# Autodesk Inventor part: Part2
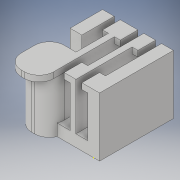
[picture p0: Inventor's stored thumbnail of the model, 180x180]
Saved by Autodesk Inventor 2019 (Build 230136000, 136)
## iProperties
Created: 2019-02
Part Number: Part2
Material: Generic
Document SubType Name: Modeling
Designer: Patel Family
Density: 1 g/cm^3
Appearance: Default
Author: Patel Family
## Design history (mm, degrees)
sketch "Sketch3"
  geometry: 1 further point
sketch "Sketch4"
  geometry: L1 (0, 0)-(10, 0); L2 (10, 0)-(10, -12.5); L3 (10, -12.5)-(0, -12.5); L4 (0, -12.5)-(0, 0)
  constraints: 8 end point, 2 parallel, 1 horizontal, 1 perpendicular
  dimensions: "d12" = 10 distance of L2.end L3.end; "d13" = 12.5 distance of L1.end L2.end
extrude "Extrusion2" new body sketch "Sketch4" distance "d14" = 2; taper "d15" = 0 deg
sketch "Sketch5"
  geometry: 1 further point
sketch "Sketch6"
  geometry: L1 (-10, 0)-(0, 0) reference; L2 (0, 0)-(-1, 0); L3 (-1, 0)-(-3, 0); L4 (-3, 0)-(-4, 0); L5 (-4, 0)-(-6, 0); L6 (-6, 0)-(-7, 0); L7 (-7, 0)-(-9, 0); L8 (-9, 0)-(-10, 0); L9 (0, 12.5)-(-10, 12.5) reference; L10 (0, 0)-(-1, 0); L11 (-1, 0)-(-1, 12.5); L12 (-1, 12.5)-(0, 12.5); L13 (0, 12.5)-(0, 0); L14 (-3, 0)-(-4, 0); L15 (-4, 0)-(-4, 12.5); L16 (-4, 12.5)-(-3, 12.5); L17 (-3, 12.5)-(-3, 0); L18 (-6, 0)-(-7, 0); L19 (-7, 12.5)-(-6, 12.5); L20 (-6, 12.5)-(-6, 0); L21 (-9, 0)-(-10, 0); L22 (-10, 0)-(-10, 12.5); L23 (-10, 12.5)-(-9, 12.5); L24 (-6, 0)-(-10, 0); L25 (-10, 0)-(-10, 4); L26 (-6, 4)-(-6, 0); L27 (-10, 12.5)-(-9, 12.5); L28 (-9, 12.5)-(-9, 6.5); L29 (-9, 6.5)-(-10, 6.5); L30 (-10, 6.5)-(-10, 12.5); L31 (-10, 4)-(-7, 4); L32 (-7, 4)-(-7, 12.5)
  constraints: 60 end point, 10 point on line, 9 parallel, 6 horizontal, 6 perpendicular, 1 collinear
  dimensions: "d16" = 1 distance of L1.end L2.end; "d17" = 2 distance of L2.end L3.end; "d18" = 1 distance of L3.end L4.end; "d19" = 2 distance of L4.end L5.end; "d20" = 1 distance of L5.end L6.end; "d21" = 2 distance of L6.end L7.end; "d22" = 1 distance of L7.end L1.start (derived); "d23" = 4 distance of L24.end L25.end; "d24" = 6 distance of L27.end L28.end
extrude "Extrusion3" join sketch "Sketch6" distance "d25" = 8; taper "d26" = 0 deg
sketch "Sketch7"
  geometry: L1 (0, 10)-(4, 10) reference; L2 (4, 2)-(4, 10) reference; L3 (0, 10)-(4, 10); L4 (4, 10)-(4, 9); L5 (4, 9)-(0, 9); L6 (0, 9)-(0, 10); 1 further point
  constraints: 8 end point, 2 parallel, 1 horizontal, 1 perpendicular, 1 point on line
  dimensions: "d27" = 1 distance of L3.end L4.end
extrude "Extrusion4" join sketch "Sketch7" distance "d28" = 2; taper "d29" = 0 deg
fillet "Fillet2" dims "d31" = 1
sketch "Sketch8"
  geometry: L1 (12.5, 0)-(12.5, 8) reference; L2 (8.5, 9)-(8.5, 1) reference
  dimensions: "d32" = 4 distance between parallel lines of L1 L2 (derived)
sketch "Sketch9"
  geometry: 1 further point
sketch "Sketch10"
  geometry: L1 (0, 10)-(8.5, 10) reference; L2 (12.5, 0)-(12.5, 10) reference; L3 (8.5, 10)-(12.5, 10); L4 (12.5, 10)-(12.5, 0); L5 (12.5, 0)-(8.5, 0); L6 (8.5, 0)-(8.5, 10)
  constraints: 8 end point, 2 parallel, 1 horizontal, 1 perpendicular
sketch "Sketch11"
  geometry: 1 further point
sketch "Sketch13"
  geometry: L1 (8.5, 2)-(8.5, 10) reference; L2 (8.5, 10)-(12.5, 10); L3 (12.5, 10)-(12.5, 0); L4 (12.5, 0)-(8.5, 0); L5 (8.5, 0)-(8.5, 10)
  constraints: 8 end point, 2 parallel, 1 horizontal, 1 perpendicular
extrude "Extrusion6" join sketch "Sketch13" distance "d36" = 1.5; taper "d37" = 0 deg
sketch "Sketch14"
  geometry: L1 (-7, 8)-(-8.5, 8) reference; L2 (-3, 0)-(-1, 0) reference; L3 (-8.5, 8)-(-3, 8); L4 (-3, 8)-(-3, 0); L5 (-3, 0)-(-8.5, 0); L6 (-8.5, 0)-(-8.5, 8); L7 (3, -2)-(-8.5, -2) reference; L8 (-3, -2)-(-8.5, -2); L9 (-8.5, -2)-(-8.5, 0); L10 (-8.5, 0)-(-3, 0); L11 (-3, 0)-(-3, -2)
  constraints: 16 end point, 4 parallel, 2 horizontal, 2 perpendicular, 2 point on line
extrude "Extrusion7" join sketch "Sketch14" distance "d38" = 1.5; taper "d39" = 0 deg
fillet "Fillet3" dims "d40" = 2.5
sketch "Sketch15"
  geometry: L1 (-4, 8)-(-3, 8) reference; L2 (-8.5, -2)-(-8.5, 8) reference; L3 (-3, 8)-(-8.5, 8); L4 (-8.5, 8)-(-8.5, 7); L5 (-8.5, 7)-(-3, 7); L6 (-3, 7)-(-3, 8); 1 further point
  constraints: 8 end point, 2 parallel, 1 horizontal, 1 perpendicular, 1 point on line
  dimensions: "d41" = 1 distance of L4.end L3.end
extrude "Extrusion8" join sketch "Sketch15" stored distance "d42" = 3.5; taper "d43" = 0 deg
fillet "Fillet4" dims "d44" = 2.5
sketch "Sketch16"
  geometry: L1 (12.5, 8)-(9.5, 8); L2 (9.5, 8)-(9.5, 7); L3 (9.5, 7)-(12.5, 7); L4 (12.5, 7)-(12.5, 8); 1 further point
  constraints: 8 end point, 2 parallel, 1 horizontal, 1 perpendicular
  dimensions: "d45" = 3 distance of L3.end L2.end; "d46" = 1 distance of L2.end L1.end
sketch "Sketch17"
  geometry: L1 (-0.69, 0.229)-(0.31, 0.229); L2 (0.31, 0.229)-(0.31, -2.771); L3 (0.31, -2.771)-(-0.69, -2.771); L4 (-0.69, -2.771)-(-0.69, 0.229); 1 further point
  constraints: 8 end point, 2 parallel, 1 horizontal, 1 perpendicular
  dimensions: "d47" = 1 distance of L2.end L3.end; "d48" = 3 distance of L1.end L2.end
sketch "Sketch18"
  geometry: L1 (12.5, -2)-(12.5, 8) reference; L2 (12.5, 8)-(9.5, 8); L3 (9.5, 8)-(9.5, 7); L4 (9.5, 7)-(12.5, 7); L5 (12.5, 7)-(12.5, 8)
  constraints: 8 end point, 2 parallel, 1 horizontal, 1 perpendicular
  dimensions: "d49" = 3 distance of L4.end L3.end; "d50" = 1 distance of L3.end L2.end
extrude "Extrusion9" join sketch "Sketch16" distance "d51" = 1; taper "d52" = 0 deg
extrude "Extrusion10" join sketch "Sketch18" distance "d53" = 1; taper "d54" = 0 deg
sketch "Sketch19"
  geometry: L1 (0, 0)-(0, 8) reference; L2 (0, 8)-(3, 8); L3 (3, 8)-(3, 7); L4 (3, 7)-(0, 7); L5 (0, 7)-(0, 8); 1 further point
  constraints: 8 end point, 2 parallel, 1 horizontal, 1 perpendicular
  dimensions: "d55" = 3 distance of L3.end L4.end; "d56" = 1 distance of L2.end L3.end
extrude "Extrusion11" join sketch "Sketch19" distance "d57" = 1; taper "d58" = 0 deg
sketch "Sketch20"
  geometry: 1 further point
sketch "Sketch21"
  geometry: L1 (12.5, 0)-(12.5, 8) reference; L2 (12.5, 8)-(9.5, 8); L3 (9.5, 8)-(9.5, 7); L4 (9.5, 7)-(12.5, 7); L5 (12.5, 7)-(12.5, 8); 1 further point
  constraints: 8 end point, 2 parallel, 1 horizontal, 1 perpendicular
  dimensions: "d59" = 3 distance of L4.end L3.end; "d60" = 1 distance of L3.end L2.end
extrude "Extrusion12" join sketch "Sketch21" distance "d61" = 1; taper "d62" = 0 deg
sketch "Sketch22"
  geometry: L1 (0, 8)-(-9.5, 8) reference; L2 (0, 8)-(-3, 8); L3 (-3, 8)-(-3, 7); L4 (-3, 7)-(0, 7); L5 (0, 7)-(0, 8); 1 further point
  constraints: 8 end point, 2 parallel, 1 horizontal, 1 perpendicular
  dimensions: "d63" = 3 distance of L4.end L3.end; "d64" = 1 distance of L3.end L2.end
extrude "Extrusion13" join sketch "Sketch22" distance "d65" = 1; taper "d66" = 0 deg
sketch "Sketch23"
  geometry: 1 further point
sketch "Sketch24"
  geometry: L1 (-9, 12.5)-(-9, 6.5) reference; L2 (-10, 3.791)-(-10, 12.5) reference; L3 (-9, 6.5)-(-10, 6.5); L4 (-10, 6.5)-(-10, 7); L5 (-10, 7)-(-9, 7); L6 (-9, 7)-(-9, 6.5); 1 further point
  constraints: 8 end point, 2 parallel, 1 horizontal, 1 perpendicular, 1 point on line
  dimensions: "d67" = 0.5 distance of L3.end L4.end
extrude "Extrusion14" cut sketch "Sketch24" distance "d68" = 8; taper "d69" = 0 deg
sketch "Sketch25"
  geometry: L1 (-0.75, 1)-(-10.25, 1) reference; L2 (2.5, 0)-(0, 0) reference; L3 (-1.981, 1)-(0, 1); L4 (0, 1)-(0, 0); L5 (0, 0)-(-1.981, 0); L6 (-1.981, 0)-(-1.981, 1); 1 further point
  constraints: 8 end point, 2 parallel, 1 horizontal, 1 perpendicular, 1 point on line
extrude "Extrusion15" cut sketch "Sketch25" distance "d70" = 0.5; taper "d71" = 0 deg
sketch "Sketch26"
  geometry: L1 (-2.25, 1)-(-1.981, 1) reference; L2 (2.5, 0)-(0, 0) reference; L3 (-1.981, 1)-(0, 1); L4 (0, 1)-(0, 0); L5 (0, 0)-(-1.981, 0); L6 (-1.981, 0)-(-1.981, 1); 1 further point
  constraints: 8 end point, 2 parallel, 1 horizontal, 1 perpendicular
extrude "Extrusion16" join sketch "Sketch26" distance "d72" = 0.5; taper "d73" = 0 deg
sketch "Sketch27"
  geometry: 1 further point
sketch "Sketch28"
  geometry: L1 (0, 0)-(0, 10) reference; L2 (12.5, 0)-(12.5, 10) reference; L3 (0, 10)-(12.5, 10); L4 (12.5, 10)-(12.5, 0); L5 (12.5, 0)-(0, 0); L6 (0, 0)-(0, 10)
  constraints: 8 end point, 2 parallel, 1 horizontal, 1 perpendicular
extrude "Extrusion17" join sketch "Sketch28" distance "d74" = 1; taper "d75" = 0 deg
sketch "Sketch29"
  geometry: L1 (0, 0)-(0, 10) reference; L2 (5.5, 10)-(5.5, 2) reference; L3 (0, 10)-(5.5, 10); L4 (5.5, 10)-(5.5, 2); L5 (5.5, 2)-(0, 2); L6 (0, 2)-(0, 10); L7 (5.5, 2)-(8.709, 2) reference; L8 (8.709, 0)-(0, 0) reference; L9 (8.709, 2)-(0, 2); L10 (0, 2)-(0, 0); L11 (0, 0)-(8.709, 0); L12 (8.709, 0)-(8.709, 2); 1 further point
  constraints: 16 end point, 4 parallel, 2 horizontal, 2 perpendicular
extrude "Extrusion18" join sketch "Sketch29" distance "d76" = 1; taper "d77" = 0 deg
sketch "Sketch30"
  geometry: L1 (8.5, 2)-(0, 2) reference; L2 (14, 0)-(11.5, 0) reference; L3 (7.764, 2)-(11.5, 2); L4 (11.5, 2)-(11.5, 0); L5 (11.5, 0)-(7.764, 0); L6 (7.764, 0)-(7.764, 2); 1 further point
  constraints: 8 end point, 2 parallel, 1 horizontal, 1 perpendicular, 1 point on line
extrude "Extrusion19" cut sketch "Sketch30" distance "d78" = 2; taper "d79" = 0 deg
sketch "Sketch31"
  geometry: L1 (7.764, 2)-(5.5, 2) reference; L2 (12.5, 2)-(12.5, 0) reference; L3 (7.764, 2)-(12.5, 2); L4 (12.5, 2)-(12.5, 0); L5 (12.5, 0)-(7.764, 0); L6 (7.764, 0)-(7.764, 2)
  constraints: 8 end point, 2 parallel, 1 horizontal, 1 perpendicular
extrude "Extrusion20" join sketch "Sketch31" distance "d80" = 2; taper "d81" = 0 deg
sketch "Sketch32"
  geometry: L1 (-17, -2)-(7.5, -2) reference; L2 (4, 8)-(1, 8) reference; 1 further point
  dimensions: "d82" = 10 distance between parallel lines of L1 L2 (derived)
sketch "Sketch33"
  geometry: 1 further point
sketch "Sketch34"
  geometry: L1 (12.5, 0)-(12.5, 10) reference; L2 (0, 10)-(0, 0) reference
  dimensions: "d83" = 12.5 distance between parallel lines of L1 L2 (derived)
sketch "Sketch35"
  geometry: L1 (1, 0)-(1, -12.5) reference; L2 (-11.5, -1.5)-(-11.5, -1) reference; L3 (-11, -12.5)-(1, -12.5) reference; L4 (-9, 1.5)-(-8.5, 1.5) reference; 1 further point
  dimensions: "d84" = 12.5 distance between parallel lines of L1 L2 (derived); "d85" = 14 distance between parallel lines of L3 L4 (derived)
sketch "Sketch1"
  geometry: L1 (0, 0)-(16.5, 0); L2 (16.5, 0)-(16.5, -12.5); L3 (16.5, -12.5)-(0, -12.5); L4 (0, -12.5)-(0, 0)
  constraints: 8 end point, 2 parallel, 1 horizontal, 1 perpendicular
  dimensions: "d0" = 16.5 distance of L2.end L3.end; "d1" = 12.5 distance of L1.end L2.end
extrude "Extrusion1" new body sketch "Sketch1" distance "d2" = 1; taper "d3" = 0 deg
sketch "Sketch2"
  geometry: L1 (-16.5, 0)-(0, 0) reference; L2 (0, 0)-(0, 12.5) reference; L3 (-16.5, 0)-(0, 0); L4 (0, 0)-(0, 1); L5 (0, 1)-(-16.5, 1); L6 (-16.5, 1)-(-16.5, 0); L7 (-16.5, 1)-(-16.5, 3); L8 (-16.5, 12.5)-(-16.5, 0) reference; L9 (-16.5, 3)-(0, 3); L10 (0, 3)-(0, 4); L11 (0, 4)-(-16.5, 4); L12 (-16.5, 4)-(-16.5, 3); L13 (-16.5, 4)-(-16.5, 6); L14 (-16.5, 6)-(-16.5, 7); L15 (-16.5, 7)-(-16.5, 9); L16 (-16.5, 9)-(-16.5, 10); L17 (-16.5, 6)-(0, 6); L18 (0, 6)-(0, 11); L19 (0, 11)-(-16.5, 11); L20 (-16.5, 11)-(-16.5, 6); L21 (0, 6)-(0, 8.5)
  constraints: 36 end point, 8 point on line, 6 parallel, 3 horizontal, 3 perpendicular, 1 midpoint
  dimensions: "d4" = 1 distance of L4.end L3.end; "d5" = 2 distance of L5.end L7.end; "d6" = 1 distance of L10.end L9.end; "d7" = 2 distance of L11.end L13.end; "d8" = 1 distance of L13.end L14.end; "d9" = 2 distance of L14.end L15.end; "d10" = 1 distance of L15.end L16.end; "d11" = 5 distance of L18.end L17.end
body "Solid1"
body "Solid2"
